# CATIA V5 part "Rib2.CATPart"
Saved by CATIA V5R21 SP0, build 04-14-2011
Part number: Rib2
Bounding box of the stored display mesh (mm): x 0 to 3, y -4.989 to 4.989, z -115 to 115
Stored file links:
  K:\Arm_Detailed_Design_Assembly_Manu\Rib2.CATPart
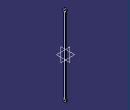
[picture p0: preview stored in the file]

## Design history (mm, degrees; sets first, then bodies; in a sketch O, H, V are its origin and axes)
Body1 (main body)
  Sketch1 on yz-plane, origin (0, 0, 0), H (0, 1, 0), V (0, 0, 1)
    arc A1 centre (0, 110) radius 5 from (3.8636, 106.8263) to (-3.8636, 106.8263) ccw
    point P1 (0, 110)
    arc A2 centre (0, -110) radius 5 from (-3.8636, -106.8263) to (3.8636, -106.8263) ccw
    point P2 (0, -110)
    line L1 (-2.5, 103.0179) -> (-2.5, -103.0179)
    point P3 (-2.5, 105.6699)
    point P4 (-2.5, -105.6699)
    point P5 (2.5, -105.6699)
    point P6 (2.5, 105.6699)
    line L2 (2.5, 103.0179) -> (2.5, -103.0179)
    arc A3 centre (8.5, 103.0179) radius 6 from (3.8636, 106.8263) to (2.5, 103.0179) ccw
    arc A4 centre (-8.5, 103.0179) radius 6 from (-3.8636, 106.8263) to (-2.5, 103.0179) cw
    arc A5 centre (8.5, -103.0179) radius 6 from (3.8636, -106.8263) to (2.5, -103.0179) cw
    arc A6 centre (-8.5, -103.0179) radius 6 from (-3.8636, -106.8263) to (-2.5, -103.0179) ccw
    circle A7 centre (0, 110) radius 1
    circle A8 centre (0, -110) radius 1
    radius A1 = 5
    distance P1 H = 110
    radius A2 = 5
    distance P2 H = 110
    distance L1 V = 2.5
    radius A3 = 6
    radius A4 = 6
    radius A5 = 6
    radius A6 = 6
    radius A7 = 1
    radius A8 = 1
    coincidence: P1 V, P2 V, A1 P6, L2 P6, A1 P3, L1 P3, A2 P5, L2 P5, A2 P4, L1 P4
    vertical: L1 V
    symmetry: P4 P5 V, P3 P6 V, L1 L2 V
    tangency: A3 A1, A3 L2, A4 A1, A4 L1, A5 L2, A5 A2, A6 L1, A6 A2
  Pad1: profile Sketch1, direction (1, 0, 0), length 3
